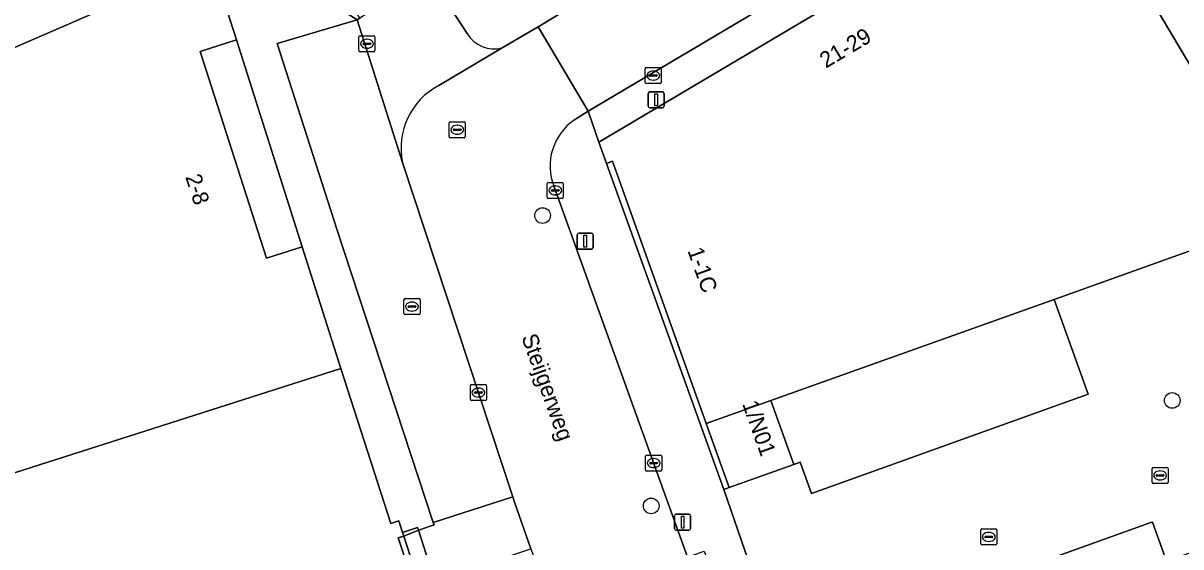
# Model space of a CAD drawing. Extents: x 159499 to 160349, y 382524 to 383273.
# Drawn here: x 159551.5 to 159623.7, y 382942.6 to 382975.3 of the extents above; entities that cross this region are included whole.
import ezdxf

# ---------------------------------------------------------------- set-up
doc = ezdxf.new("R2010")
doc.units = 0
for name, color, linetype in [('IMGEO_Boom', 7, 'Continuous'), ('IMGEO_Kolk', 7, 'Continuous'), ('IMGEO_Lichtmast', 7, 'Continuous'), ('IMGEO_Openbare_ruimte_label', 7, 'Continuous'), ('IMGEO_Pand', 7, 'Continuous'), ('IMGEO_Pand_nummerreeks', 7, 'Continuous'), ('IMGEO_Pand_overbouw', 7, 'Continuous'), ('IMGEO_Parkeervlak_open', 7, 'Continuous'), ('IMGEO_Rijbaan_lokaal_open', 7, 'Continuous'), ('IMGEO_Rioolput', 7, 'Continuous'), ('IMGEO_Voetpad_open', 7, 'Continuous')]:
    doc.layers.add(name, color=color, linetype=linetype)

msp = doc.modelspace()

# ---------------------------------------------------------------- linework, layer by layer
at = {"layer": 'IMGEO_Boom'}
for centre in [(159583.86, 382963.269), (159623.146, 382951.719), (159590.637, 382945.135)]:
    msp.add_circle(centre, 0.489, dxfattribs=at)
at = {"layer": 'IMGEO_Kolk'}
for p, q in [((159572.402, 382973.57), (159572.402, 382974.422)), ((159572.477, 382974.496), (159573.329, 382974.496)), ((159572.661, 382973.99), (159572.661, 382974.002)), ((159572.704, 382974.039), (159573.102, 382974.039)), ((159572.89, 382974.276), (159572.915, 382974.276)), ((159573.145, 382974.002), (159573.145, 382973.99)), ((159573.403, 382974.422), (159573.403, 382973.57)), ((159573.329, 382973.496), (159572.477, 382973.496)), ((159573.099, 382973.953), (159572.701, 382973.953)), ((159572.913, 382973.716), (159572.888, 382973.716)), ((159590.267, 382971.582), (159590.267, 382972.434)), ((159590.342, 382972.508), (159591.194, 382972.508)), ((159590.526, 382972.002), (159590.526, 382972.014)), ((159590.964, 382971.965), (159590.566, 382971.965)), ((159590.569, 382972.051), (159590.967, 382972.051)), ((159590.755, 382972.288), (159590.78, 382972.288)), ((159591.01, 382972.014), (159591.01, 382972.002)), ((159591.268, 382972.434), (159591.268, 382971.582)), ((159591.194, 382971.508), (159590.342, 382971.508)), ((159590.778, 382971.728), (159590.753, 382971.728)), ((159584.228, 382965.339), (159585.08, 382965.339)), ((159584.153, 382964.413), (159584.153, 382965.265)), ((159584.412, 382964.833), (159584.412, 382964.845)), ((159584.85, 382964.796), (159584.452, 382964.796)), ((159584.455, 382964.882), (159584.853, 382964.882)), ((159584.641, 382965.119), (159584.666, 382965.119)), ((159584.896, 382964.845), (159584.896, 382964.833)), ((159585.154, 382965.265), (159585.154, 382964.413)), ((159585.08, 382964.339), (159584.228, 382964.339)), ((159584.664, 382964.559), (159584.639, 382964.559)), ((159579.353, 382951.785), (159579.353, 382952.637)), ((159579.428, 382952.711), (159580.28, 382952.711)), ((159579.841, 382952.491), (159579.866, 382952.491)), ((159580.354, 382952.637), (159580.354, 382951.785)), ((159580.28, 382951.711), (159579.428, 382951.711)), ((159579.612, 382952.205), (159579.612, 382952.217)), ((159580.05, 382952.168), (159579.652, 382952.168)), ((159579.655, 382952.254), (159580.053, 382952.254)), ((159579.864, 382951.931), (159579.839, 382951.931)), ((159580.096, 382952.217), (159580.096, 382952.205)), ((159590.289, 382947.385), (159590.289, 382948.237)), ((159590.364, 382948.311), (159591.216, 382948.311)), ((159590.777, 382948.091), (159590.802, 382948.091)), ((159591.29, 382948.237), (159591.29, 382947.385)), ((159591.216, 382947.311), (159590.364, 382947.311)), ((159590.548, 382947.805), (159590.548, 382947.817)), ((159590.986, 382947.768), (159590.588, 382947.768)), ((159590.591, 382947.854), (159590.989, 382947.854)), ((159590.8, 382947.531), (159590.775, 382947.531)), ((159591.032, 382947.817), (159591.032, 382947.805)), ((159621.888, 382946.615), (159621.888, 382947.467)), ((159621.963, 382947.541), (159622.815, 382947.541)), ((159622.376, 382947.321), (159622.401, 382947.321)), ((159622.889, 382947.467), (159622.889, 382946.615)), ((159622.147, 382947.035), (159622.147, 382947.047)), ((159622.585, 382946.998), (159622.187, 382946.998)), ((159622.19, 382947.084), (159622.588, 382947.084)), ((159622.399, 382946.761), (159622.374, 382946.761)), ((159622.631, 382947.047), (159622.631, 382947.035)), ((159622.815, 382946.541), (159621.963, 382946.541)), ((159611.276, 382943.702), (159612.128, 382943.702)), ((159611.201, 382942.776), (159611.201, 382943.628)), ((159611.46, 382943.196), (159611.46, 382943.208)), ((159611.898, 382943.159), (159611.5, 382943.159)), ((159611.503, 382943.245), (159611.901, 382943.245)), ((159611.689, 382943.482), (159611.714, 382943.482)), ((159611.944, 382943.208), (159611.944, 382943.196)), ((159612.202, 382943.628), (159612.202, 382942.776)), ((159612.128, 382942.702), (159611.276, 382942.702)), ((159611.712, 382942.922), (159611.687, 382942.922))]:
    msp.add_line(p, q, dxfattribs=at)
for points in [[(159572.402, 382973.57), (159572.402, 382974.422)], [(159572.477, 382974.496), (159573.329, 382974.496)], [(159573.403, 382974.422), (159573.403, 382973.57)], [(159573.329, 382973.496), (159572.477, 382973.496)], [(159590.267, 382971.582), (159590.267, 382972.434)], [(159590.342, 382972.508), (159591.194, 382972.508)], [(159591.268, 382972.434), (159591.268, 382971.582)], [(159591.194, 382971.508), (159590.342, 382971.508)], [(159584.228, 382965.339), (159585.08, 382965.339)], [(159584.153, 382964.413), (159584.153, 382965.265)], [(159585.154, 382965.265), (159585.154, 382964.413)], [(159585.08, 382964.339), (159584.228, 382964.339)], [(159579.353, 382951.785), (159579.353, 382952.637)], [(159579.428, 382952.711), (159580.28, 382952.711)], [(159580.354, 382952.637), (159580.354, 382951.785)], [(159580.28, 382951.711), (159579.428, 382951.711)], [(159590.289, 382947.385), (159590.289, 382948.237)], [(159590.364, 382948.311), (159591.216, 382948.311)], [(159591.29, 382948.237), (159591.29, 382947.385)], [(159591.216, 382947.311), (159590.364, 382947.311)], [(159621.888, 382946.615), (159621.888, 382947.467)], [(159621.963, 382947.541), (159622.815, 382947.541)], [(159622.889, 382947.467), (159622.889, 382946.615)], [(159622.815, 382946.541), (159621.963, 382946.541)], [(159611.276, 382943.702), (159612.128, 382943.702)], [(159611.201, 382942.776), (159611.201, 382943.628)], [(159612.202, 382943.628), (159612.202, 382942.776)], [(159612.128, 382942.702), (159611.276, 382942.702)]]:
    msp.add_lwpolyline(points, dxfattribs=at)
for centre, radius, start, end in [((159572.479, 382974.42), 0.0765, 91.55205, 178.44795), ((159572.479, 382974.42), 0.0765, 91.55205, 178.44795), ((159572.701, 382973.999), 0.0403, 85.87752, 175.75265), ((159572.698, 382973.989), 0.0366, 178.93798, 274.71019), ((159573.102, 382973.996), 0.043, 264.86636, 352.45326), ((159573.106, 382974.001), 0.0386, 1.73085, 96.63898), ((159573.327, 382974.42), 0.0765, 1.55205, 88.44795), ((159573.327, 382974.42), 0.0765, 1.55205, 88.44795), ((159572.479, 382973.572), 0.0765, 181.55205, 268.44795), ((159572.479, 382973.572), 0.0765, 181.55205, 268.44795), ((159573.327, 382973.572), 0.0765, 271.55205, 358.44795), ((159573.327, 382973.572), 0.0765, 271.55205, 358.44795), ((159590.344, 382972.432), 0.0765, 91.55205, 178.44795), ((159590.344, 382972.432), 0.0765, 91.55205, 178.44795), ((159590.566, 382972.011), 0.0403, 85.87752, 175.75265), ((159590.563, 382972.001), 0.0366, 178.93798, 274.71019), ((159590.967, 382972.008), 0.043, 264.86636, 352.45326), ((159590.971, 382972.013), 0.0386, 1.73085, 96.63898), ((159591.192, 382972.432), 0.0765, 1.55205, 88.44795), ((159591.192, 382972.432), 0.0765, 1.55205, 88.44795), ((159590.344, 382971.584), 0.0765, 181.55205, 268.44795), ((159590.344, 382971.584), 0.0765, 181.55205, 268.44795), ((159591.192, 382971.584), 0.0765, 271.55205, 358.44795), ((159591.192, 382971.584), 0.0765, 271.55205, 358.44795), ((159584.23, 382965.263), 0.0765, 91.55205, 178.44795), ((159584.23, 382965.263), 0.0765, 91.55205, 178.44795), ((159585.078, 382965.263), 0.0765, 1.55205, 88.44795), ((159585.078, 382965.263), 0.0765, 1.55205, 88.44795), ((159584.452, 382964.842), 0.0403, 85.87752, 175.75265), ((159584.449, 382964.832), 0.0366, 178.93798, 274.71019), ((159584.853, 382964.839), 0.043, 264.86636, 352.45326), ((159584.857, 382964.844), 0.0386, 1.73085, 96.63898), ((159584.23, 382964.415), 0.0765, 181.55205, 268.44795), ((159584.23, 382964.415), 0.0765, 181.55205, 268.44795), ((159585.078, 382964.415), 0.0765, 271.55205, 358.44795), ((159585.078, 382964.415), 0.0765, 271.55205, 358.44795), ((159579.43, 382952.635), 0.0765, 91.55205, 178.44795), ((159579.43, 382952.635), 0.0765, 91.55205, 178.44795), ((159580.278, 382952.635), 0.0765, 1.55205, 88.44795), ((159580.278, 382952.635), 0.0765, 1.55205, 88.44795), ((159579.43, 382951.787), 0.0765, 181.55205, 268.44795), ((159579.43, 382951.787), 0.0765, 181.55205, 268.44795), ((159579.652, 382952.214), 0.0403, 85.87752, 175.75265), ((159579.649, 382952.204), 0.0366, 178.93798, 274.71019), ((159580.053, 382952.211), 0.043, 264.86636, 352.45326), ((159580.057, 382952.216), 0.0386, 1.73085, 96.63898), ((159580.278, 382951.787), 0.0765, 271.55205, 358.44795), ((159580.278, 382951.787), 0.0765, 271.55205, 358.44795), ((159590.366, 382948.235), 0.0765, 91.55205, 178.44795), ((159590.366, 382948.235), 0.0765, 91.55205, 178.44795), ((159591.214, 382948.235), 0.0765, 1.55205, 88.44795), ((159591.214, 382948.235), 0.0765, 1.55205, 88.44795), ((159590.366, 382947.387), 0.0765, 181.55205, 268.44795), ((159590.366, 382947.387), 0.0765, 181.55205, 268.44795), ((159590.588, 382947.814), 0.0403, 85.87752, 175.75265), ((159590.585, 382947.804), 0.0366, 178.93798, 274.71019), ((159590.989, 382947.811), 0.043, 264.86636, 352.45326), ((159590.993, 382947.816), 0.0386, 1.73085, 96.63898), ((159591.214, 382947.387), 0.0765, 271.55205, 358.44795), ((159591.214, 382947.387), 0.0765, 271.55205, 358.44795), ((159621.965, 382947.465), 0.0765, 91.55205, 178.44795), ((159621.965, 382947.465), 0.0765, 91.55205, 178.44795), ((159622.813, 382947.465), 0.0765, 1.55205, 88.44795), ((159622.813, 382947.465), 0.0765, 1.55205, 88.44795), ((159621.965, 382946.617), 0.0765, 181.55205, 268.44795), ((159621.965, 382946.617), 0.0765, 181.55205, 268.44795), ((159622.187, 382947.044), 0.0403, 85.87752, 175.75265), ((159622.184, 382947.034), 0.0366, 178.93798, 274.71019), ((159622.588, 382947.041), 0.043, 264.86636, 352.45326), ((159622.592, 382947.046), 0.0386, 1.73085, 96.63898), ((159622.813, 382946.617), 0.0765, 271.55205, 358.44795), ((159622.813, 382946.617), 0.0765, 271.55205, 358.44795), ((159611.278, 382943.626), 0.0765, 91.55205, 178.44795), ((159611.278, 382943.626), 0.0765, 91.55205, 178.44795), ((159612.126, 382943.626), 0.0765, 1.55205, 88.44795), ((159612.126, 382943.626), 0.0765, 1.55205, 88.44795), ((159611.5, 382943.205), 0.0403, 85.87752, 175.75265), ((159611.497, 382943.195), 0.0366, 178.93798, 274.71019), ((159611.901, 382943.202), 0.043, 264.86636, 352.45326), ((159611.905, 382943.207), 0.0386, 1.73085, 96.63898), ((159611.278, 382942.778), 0.0765, 181.55205, 268.44795), ((159611.278, 382942.778), 0.0765, 181.55205, 268.44795), ((159612.126, 382942.778), 0.0765, 271.55205, 358.44795), ((159612.126, 382942.778), 0.0765, 271.55205, 358.44795)]:
    msp.add_arc(centre, radius, start, end, dxfattribs=at)
for centre, major_axis, ratio, start_param, end_param in [((159572.889, 382973.996), (-0.387, 0.002), 0.722429, 4.712389, 7.853982), ((159572.914, 382973.996), (-0.39, 0.002), 0.717154, 1.570796, 4.712389), ((159590.754, 382972.008), (-0.387, 0.002), 0.722429, 4.712389, 7.853982), ((159590.779, 382972.008), (-0.39, 0.002), 0.717154, 1.570796, 4.712389), ((159584.64, 382964.839), (-0.387, 0.002), 0.722429, 4.712389, 7.853982), ((159584.665, 382964.839), (-0.39, 0.002), 0.717154, 1.570796, 4.712389), ((159579.84, 382952.211), (-0.387, 0.002), 0.722429, 4.712389, 7.853982), ((159579.865, 382952.211), (-0.39, 0.002), 0.717154, 1.570796, 4.712389), ((159590.776, 382947.811), (-0.387, 0.002), 0.722429, 4.712389, 7.853982), ((159590.801, 382947.811), (-0.39, 0.002), 0.717154, 1.570796, 4.712389), ((159622.375, 382947.041), (-0.387, 0.002), 0.722429, 4.712389, 7.853982), ((159622.4, 382947.041), (-0.39, 0.002), 0.717154, 1.570796, 4.712389), ((159611.688, 382943.202), (-0.387, 0.002), 0.722429, 4.712389, 7.853982), ((159611.713, 382943.202), (-0.39, 0.002), 0.717154, 1.570796, 4.712389)]:
    msp.add_ellipse(centre, major_axis=major_axis, ratio=ratio, start_param=start_param, end_param=end_param, dxfattribs=at)
at = {"layer": 'IMGEO_Lichtmast'}
for p, q in [((159590.451, 382970.09), (159590.451, 382970.89)), ((159590.451, 382970.89), (159590.451, 382970.09)), ((159590.551, 382970.99), (159591.341, 382970.99)), ((159591.341, 382970.99), (159590.551, 382970.99)), ((159591.441, 382970.89), (159591.441, 382970.09)), ((159591.441, 382970.09), (159591.441, 382970.89)), ((159591.341, 382969.99), (159590.551, 382969.99)), ((159590.551, 382969.99), (159591.341, 382969.99)), ((159586.022, 382961.272), (159586.022, 382962.072)), ((159586.022, 382962.072), (159586.022, 382961.272)), ((159586.122, 382962.172), (159586.912, 382962.172)), ((159586.912, 382962.172), (159586.122, 382962.172)), ((159587.012, 382962.072), (159587.012, 382961.272)), ((159587.012, 382961.272), (159587.012, 382962.072)), ((159586.912, 382961.172), (159586.122, 382961.172)), ((159586.122, 382961.172), (159586.912, 382961.172)), ((159592.101, 382943.723), (159592.101, 382944.523)), ((159592.101, 382944.523), (159592.101, 382943.723)), ((159592.201, 382944.623), (159592.991, 382944.623)), ((159592.991, 382944.623), (159592.201, 382944.623)), ((159593.091, 382944.523), (159593.091, 382943.723)), ((159593.091, 382943.723), (159593.091, 382944.523)), ((159592.991, 382943.623), (159592.201, 382943.623)), ((159592.201, 382943.623), (159592.991, 382943.623))]:
    msp.add_line(p, q, dxfattribs=at)
for points in [[(159590.871, 382970.865), (159591.021, 382970.865), (159591.021, 382970.115), (159590.871, 382970.115), (159590.871, 382970.865)], [(159586.442, 382962.047), (159586.592, 382962.047), (159586.592, 382961.297), (159586.442, 382961.297), (159586.442, 382962.047)], [(159592.521, 382944.498), (159592.671, 382944.498), (159592.671, 382943.748), (159592.521, 382943.748), (159592.521, 382944.498)]]:
    msp.add_lwpolyline(points, dxfattribs=at)
for centre, start, end in [((159590.551, 382970.89), 90, 180), ((159590.551, 382970.89), 90, 180), ((159591.341, 382970.89), 0, 90), ((159591.341, 382970.89), 360, 90), ((159590.551, 382970.09), 180, 270), ((159590.551, 382970.09), 180, 270), ((159591.341, 382970.09), 270, 0), ((159591.341, 382970.09), 270, 0), ((159586.122, 382962.072), 90, 180), ((159586.122, 382962.072), 90, 180), ((159586.912, 382962.072), 0, 90), ((159586.912, 382962.072), 360, 90), ((159586.122, 382961.272), 180, 270), ((159586.122, 382961.272), 180, 270), ((159586.912, 382961.272), 270, 0), ((159586.912, 382961.272), 270, 0), ((159592.201, 382944.523), 90, 180), ((159592.201, 382944.523), 90, 180), ((159592.991, 382944.523), 0, 90), ((159592.991, 382944.523), 360, 90), ((159592.201, 382943.723), 180, 270), ((159592.201, 382943.723), 180, 270), ((159592.991, 382943.723), 270, 0), ((159592.991, 382943.723), 270, 0)]:
    msp.add_arc(centre, 0.1, start, end, dxfattribs=at)
at = {"layer": 'IMGEO_Pand'}
for points in [[(159538.52, 382968.383), (159563.21, 382979.1), (159565.208, 382980.005), (159562.875, 382985.371), (159556.514, 383000), (159555.064, 383003.326), (159551.308, 383011.943), (159551.107, 383011.856), (159544.127, 383003.413), (159543.752, 383003.257), (159544.561, 383001.309), (159542.463, 383000.389), (159542.31, 383000), (159541.147, 382997.049), (159542.15, 382994.77), (159540.899, 382991.583), (159538.596, 382990.53), (159537.263, 382987.168), (159538.193, 382985.055), (159536.808, 382984.454), (159536.975, 382984.056), (159538.429, 382968.666)], [(159616.76, 382985.295), (159629.938, 382963.1), (159647.373, 382969.363), (159632.4, 382994.581)], [(159594.075, 382950.274), (159598.105, 382951.722), (159615.784, 382958.015), (159629.938, 382963.1), (159616.76, 382985.295), (159587.366, 382967.842), (159587.852, 382966.52), (159588.22, 382966.653)], [(159538.52, 382968.383), (159545.874, 382945.595), (159571.265, 382953.723), (159568.852, 382961.323), (159566.639, 382960.597), (159562.49, 382973.512), (159564.758, 382974.237), (159563.21, 382979.1)], [(159622.779, 382941.693), (159621.91, 382944.124), (159621.758, 382944.07), (159613.077, 382940.968), (159614.525, 382937.123), (159605.702, 382933.97), (159605.077, 382935.718), (159604.805, 382935.62), (159604.862, 382935.46), (159606.674, 382930.391), (159609.134, 382923.507), (159680.442, 382948.993), (159676.134, 382961.046), (159676.022, 382961.006), (159675.913, 382960.967), (159676.004, 382960.713), (159676.516, 382959.279), (159624.918, 382940.838), (159623.292, 382940.257)], [(159599.538, 382947.731), (159599.932, 382947.873), (159600.634, 382945.918), (159617.901, 382952.121), (159615.784, 382958.015), (159598.105, 382951.722)], [(159571.265, 382953.723), (159545.874, 382945.595), (159547.458, 382940.666), (159550.597, 382930.894), (159557.842, 382908.578), (159562.246, 382909.987), (159561.933, 382910.967), (159566.429, 382912.413), (159569.741, 382913.479), (159578.417, 382916.191), (159582.89, 382917.624), (159579.035, 382929.541), (159579.526, 382929.703), (159578.31, 382933.501), (159576.401, 382939.467), (159576.097, 382939.369), (159574.851, 382943.147), (159575.2, 382943.254), (159575.129, 382943.477), (159574.901, 382944.198), (159574.389, 382944.03)], [(159599.538, 382947.731), (159598.105, 382951.722), (159594.075, 382950.274), (159595.502, 382946.282)]]:
    msp.add_lwpolyline(points, close=True, dxfattribs=at)
at = {"layer": 'IMGEO_Pand_overbouw'}
msp.add_lwpolyline([(159568.852, 382961.323), (159564.758, 382974.237), (159562.49, 382973.512), (159566.639, 382960.597)], close=True, dxfattribs=at)
at = {"layer": 'IMGEO_Parkeervlak_open'}
msp.add_lwpolyline([(159575.122, 382966.572), (159572.292, 382975.496), (159567.304, 382974.008), (159571.02, 382962.408), (159577.04, 382944.103), (159582.001, 382945.695)], close=True, dxfattribs=at)
msp.add_lwpolyline([(159629.938, 382963.1), (159615.784, 382958.015), (159617.901, 382952.121), (159600.634, 382945.918), (159599.932, 382947.873), (159599.538, 382947.731), (159595.502, 382946.282), (159595.17, 382946.154), (159596.475, 382942.342), (159598.947, 382935.371), (159599.544, 382935.578), (159599.377, 382936.036), (159613.077, 382940.968), (159621.758, 382944.07), (159621.91, 382944.124), (159622.779, 382941.693), (159667.453, 382957.657)], dxfattribs=at)
at = {"layer": 'IMGEO_Rijbaan_lokaal_open'}
for points in [[(159724.205, 383058.665), (159687.242, 383036.582), (159585.591, 382976.257), (159583.575, 382975.061), (159586.71, 382969.778), (159719.236, 383048.422)], [(159579.153, 382974.634), (159576.731, 382978.377), (159572.457, 382975.603), (159572.292, 382975.496), (159575.122, 382966.572)], [(159585.847, 382969.246), (159586.71, 382969.778), (159583.575, 382975.061), (159581.339, 382973.734), (159577.394, 382971.393)], [(159577.394, 382971.393), (159581.339, 382973.734)], [(159575.122, 382966.572), (159582.001, 382945.695), (159582.084, 382945.442), (159583.137, 382942.457), (159591.263, 382919.413)], [(159594.658, 382934.67), (159595.408, 382934.964), (159595.295, 382935.281), (159592.904, 382941.945), (159584.573, 382965.063)]]:
    msp.add_lwpolyline(points, dxfattribs=at)
for centre, radius, start, end in [((159580.845, 382975.638), 1.968, 210.69882, 284.54618), ((159579.43, 382967.488), 4.404, 117.53649, 191.99718), ((159579.43, 382967.488), 4.404, 117.53649, 191.99718), ((159587.833, 382966.356), 3.507, 124.48819, 201.6339)]:
    msp.add_arc(centre, radius, start, end, dxfattribs=at)
at = {"layer": 'IMGEO_Rioolput'}
for p, q in [((159578.036, 382968.201), (159578.036, 382969.053)), ((159578.111, 382969.127), (159578.963, 382969.127)), ((159579.037, 382969.053), (159579.037, 382968.201)), ((159578.295, 382968.621), (159578.295, 382968.633)), ((159578.733, 382968.584), (159578.335, 382968.584)), ((159578.338, 382968.67), (159578.736, 382968.67)), ((159578.547, 382968.347), (159578.522, 382968.347)), ((159578.524, 382968.907), (159578.549, 382968.907)), ((159578.779, 382968.633), (159578.779, 382968.621)), ((159578.963, 382968.127), (159578.111, 382968.127)), ((159575.212, 382957.157), (159575.212, 382958.009)), ((159575.287, 382958.083), (159576.139, 382958.083)), ((159575.471, 382957.577), (159575.471, 382957.589)), ((159575.909, 382957.54), (159575.511, 382957.54)), ((159575.514, 382957.626), (159575.912, 382957.626)), ((159575.7, 382957.863), (159575.725, 382957.863)), ((159575.955, 382957.589), (159575.955, 382957.577)), ((159576.213, 382958.009), (159576.213, 382957.157)), ((159576.139, 382957.083), (159575.287, 382957.083)), ((159575.723, 382957.303), (159575.698, 382957.303))]:
    msp.add_line(p, q, dxfattribs=at)
for points in [[(159578.036, 382968.201), (159578.036, 382969.053)], [(159578.111, 382969.127), (159578.963, 382969.127)], [(159579.037, 382969.053), (159579.037, 382968.201)], [(159578.963, 382968.127), (159578.111, 382968.127)], [(159575.212, 382957.157), (159575.212, 382958.009)], [(159575.287, 382958.083), (159576.139, 382958.083)], [(159576.213, 382958.009), (159576.213, 382957.157)], [(159576.139, 382957.083), (159575.287, 382957.083)]]:
    msp.add_lwpolyline(points, dxfattribs=at)
for centre, radius, start, end in [((159578.113, 382969.051), 0.0765, 91.55205, 178.44795), ((159578.113, 382969.051), 0.0765, 91.55205, 178.44795), ((159578.961, 382969.051), 0.0765, 1.55205, 88.44795), ((159578.961, 382969.051), 0.0765, 1.55205, 88.44795), ((159578.335, 382968.63), 0.0403, 85.87752, 175.75265), ((159578.332, 382968.62), 0.0366, 178.93798, 274.71019), ((159578.736, 382968.627), 0.043, 264.86636, 352.45326), ((159578.74, 382968.632), 0.0386, 1.73085, 96.63898), ((159578.113, 382968.203), 0.0765, 181.55205, 268.44795), ((159578.113, 382968.203), 0.0765, 181.55205, 268.44795), ((159578.961, 382968.203), 0.0765, 271.55205, 358.44795), ((159578.961, 382968.203), 0.0765, 271.55205, 358.44795), ((159575.289, 382958.007), 0.0765, 91.55205, 178.44795), ((159575.289, 382958.007), 0.0765, 91.55205, 178.44795), ((159575.511, 382957.586), 0.0403, 85.87752, 175.75265), ((159575.508, 382957.576), 0.0366, 178.93798, 274.71019), ((159575.912, 382957.583), 0.043, 264.86636, 352.45326), ((159575.916, 382957.588), 0.0386, 1.73085, 96.63898), ((159576.137, 382958.007), 0.0765, 1.55205, 88.44795), ((159576.137, 382958.007), 0.0765, 1.55205, 88.44795), ((159575.289, 382957.159), 0.0765, 181.55205, 268.44795), ((159575.289, 382957.159), 0.0765, 181.55205, 268.44795), ((159576.137, 382957.159), 0.0765, 271.55205, 358.44795), ((159576.137, 382957.159), 0.0765, 271.55205, 358.44795)]:
    msp.add_arc(centre, radius, start, end, dxfattribs=at)
for centre, major_axis, ratio, start_param, end_param in [((159578.523, 382968.627), (-0.387, 0.002), 0.722429, 4.712389, 7.853982), ((159578.548, 382968.627), (-0.39, 0.002), 0.717154, 1.570796, 4.712389), ((159575.699, 382957.583), (-0.387, 0.002), 0.722429, 4.712389, 7.853982), ((159575.724, 382957.583), (-0.39, 0.002), 0.717154, 1.570796, 4.712389)]:
    msp.add_ellipse(centre, major_axis=major_axis, ratio=ratio, start_param=start_param, end_param=end_param, dxfattribs=at)
at = {"layer": 'IMGEO_Voetpad_open'}
for points in [[(159719.236, 383048.422), (159586.71, 382969.778), (159587.366, 382967.842), (159616.76, 382985.295), (159632.4, 382994.581)], [(159555.492, 383014.686), (159552.985, 383013.033), (159558.003, 383005.149), (159568.247, 382988.759), (159572.27, 382982.509), (159570.807, 382982.041), (159567.995, 382981.142), (159565.208, 382980.005), (159572.292, 382975.496), (159572.457, 382975.603), (159571.96, 382976.42), (159576.224, 382979.161), (159576.731, 382978.377), (159579.153, 382974.634)], [(159581.339, 382973.734), (159583.575, 382975.061), (159585.591, 382976.257), (159584.314, 382978.537), (159580.736, 382976.534), (159580.891, 382976.254), (159580.524, 382976.049), (159571.589, 382989.915), (159565.97, 382998.562), (159555.492, 383014.686)], [(159602.33, 382925.83), (159598.947, 382935.371), (159596.475, 382942.342), (159595.17, 382946.154), (159587.852, 382966.52), (159587.366, 382967.842), (159586.71, 382969.778), (159585.847, 382969.246)], [(159584.573, 382965.063), (159592.904, 382941.945), (159593.933, 382942.303), (159596.329, 382935.67), (159595.295, 382935.281), (159595.408, 382934.964), (159594.658, 382934.67)]]:
    msp.add_lwpolyline(points, dxfattribs=at)
for points in [[(159565.208, 382980.005), (159563.21, 382979.1), (159564.758, 382974.237), (159568.852, 382961.323), (159571.265, 382953.723), (159574.389, 382944.03), (159574.901, 382944.198), (159575.129, 382943.477), (159576.065, 382943.784), (159576.117, 382943.621), (159577.091, 382943.948), (159577.04, 382944.103), (159571.02, 382962.408), (159567.304, 382974.008), (159572.292, 382975.496)], [(159562.49, 382973.512), (159566.639, 382960.597), (159568.852, 382961.323), (159564.758, 382974.237)], [(159595.17, 382946.154), (159595.502, 382946.282), (159594.075, 382950.274), (159588.22, 382966.653), (159587.852, 382966.52)], [(159582.001, 382945.695), (159577.04, 382944.103), (159577.091, 382943.948), (159576.117, 382943.621), (159577.077, 382940.619), (159578.083, 382940.937), (159578.122, 382940.788), (159583.137, 382942.457), (159582.084, 382945.442)], [(159576.117, 382943.621), (159576.065, 382943.784), (159575.129, 382943.477), (159575.2, 382943.254)], [(159576.141, 382940.323), (159575.2, 382943.254), (159574.851, 382943.147), (159576.097, 382939.369), (159576.401, 382939.467)], [(159576.141, 382940.323), (159577.077, 382940.619), (159576.117, 382943.621), (159575.2, 382943.254)]]:
    msp.add_lwpolyline(points, close=True, dxfattribs=at)
for centre, radius, start, end in [((159580.845, 382975.638), 1.968, 210.69882, 284.54618), ((159587.833, 382966.356), 3.507, 124.48819, 201.6339)]:
    msp.add_arc(centre, radius, start, end, dxfattribs=at)

# ---------------------------------------------------------------- texts
at = {"layer": 'IMGEO_Openbare_ruimte_label'}
msp.add_text('Steijgerweg', height=1, rotation=289.70395, dxfattribs=at).set_placement((159582.529, 382955.674))
at = {"layer": 'IMGEO_Pand_nummerreeks'}
for s, rotation, p in [('21-29', 30.70017, (159601.531, 382972.438)), ('2-8', 287.80984, (159561.56, 382965.683)), ('1-1C', 289.67044, (159592.889, 382961.078)), ('1/N01', 289.57313, (159596.305, 382951.517))]:
    msp.add_text(s, height=1, rotation=rotation, dxfattribs=at).set_placement(p)

doc.saveas('drawing.dxf')
